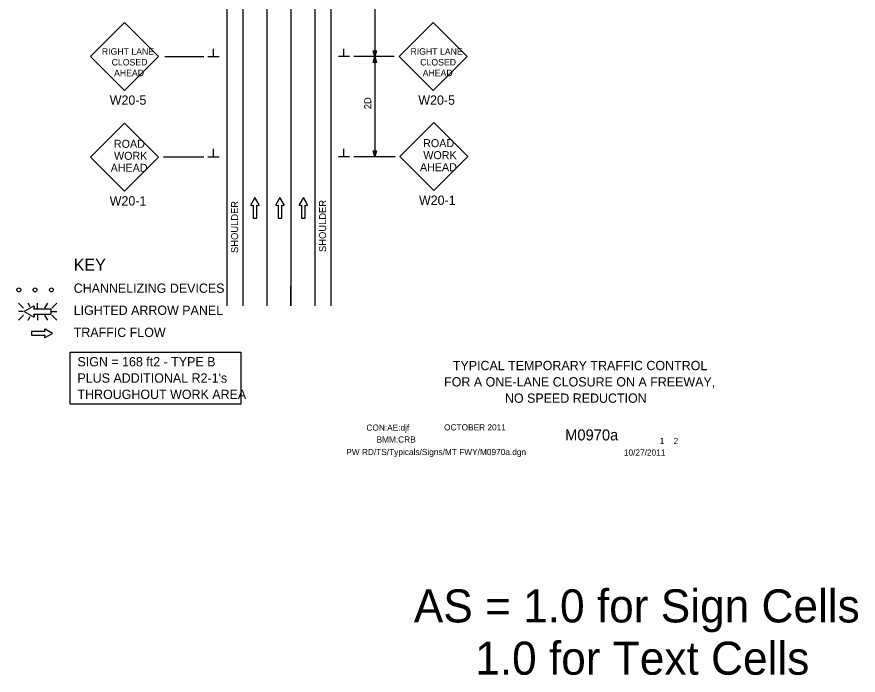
# Model space of a CAD drawing. Extents: x 16741 to 18475, y 7000 to 8315.
# Drawn here: x 16741 to 17582, y 7000 to 7658 of the extents above; entities that cross this region are included whole.
import ezdxf

# ---------------------------------------------------------------- set-up
doc = ezdxf.new("R2010")
doc.units = 0
for name, color, linetype in [('ALI_LEGAL_EX', 7, 'Continuous'), ('BORDER', 7, 'Continuous'), ('BORDER_SIGNAL_WO', 7, 'Continuous'), ('MT_SCRATCH_LEVEL_E', 7, 'Continuous'), ('PAVT_EDGE_EX', 7, 'Continuous'), ('TRAFFIC_SIGNS_PR', 7, 'Continuous'), ('TYPICAL_TEXT_DIMEN_EX', 7, 'Continuous'), ('TYPICAL_TEXT_DIMEN_PR', 7, 'Continuous')]:
    doc.layers.add(name, color=color, linetype=linetype)

msp = doc.modelspace()

# ---------------------------------------------------------------- linework, layer by layer
at = {"layer": 'ALI_LEGAL_EX'}
for p, q in [((16991.15, 8188.6), (16991.15, 7369.05)), ((17015.15, 8188.6), (17015.15, 7369.05))]:
    msp.add_line(p, q, dxfattribs=at)
for points in [[(16991.15, 7588.6), (16991.15, 7563.6)], [(17015.15, 7588.6), (17015.15, 7563.6)], [(16991.15, 7488.6), (16991.15, 7463.6)], [(17015.15, 7488.6), (17015.15, 7463.6)], [(16991.15, 7388.6), (16991.15, 7369.05)], [(17015.15, 7369.05), (17015.15, 7388.6)], [(17015.15, 7369.05), (17015.15, 7388.6)]]:
    msp.add_lwpolyline(points, dxfattribs=at)
at = {"layer": 'MT_SCRATCH_LEVEL_E'}
for p, q in [((16979.32, 7477.44), (16975.21, 7470.2)), ((16983.46, 7470.2), (16979.32, 7477.44)), ((17004.27, 7477.44), (17000.16, 7470.2)), ((17008.42, 7470.2), (17004.27, 7477.44)), ((17027.68, 7477.44), (17023.57, 7470.2)), ((17031.83, 7470.2), (17027.68, 7477.44)), ((16975.69, 7469.52), (16977.46, 7469.84)), ((16977.46, 7469.84), (16977.46, 7456.58)), ((16981.21, 7456.58), (16981.21, 7469.84)), ((16981.21, 7469.84), (16982.98, 7469.52)), ((17000.64, 7469.52), (17002.42, 7469.84)), ((17002.42, 7469.84), (17002.42, 7456.58)), ((17006.16, 7456.58), (17006.16, 7469.84)), ((17006.16, 7469.84), (17007.94, 7469.52)), ((17024.05, 7469.52), (17025.83, 7469.84)), ((17025.83, 7469.84), (17025.83, 7456.58)), ((17029.57, 7456.58), (17029.57, 7469.84)), ((17029.57, 7469.84), (17031.35, 7469.52)), ((16977.46, 7456.58), (16981.21, 7456.58)), ((17002.42, 7456.58), (17006.16, 7456.58)), ((17025.83, 7456.58), (17029.57, 7456.58)), ((16769.4, 7343.46), (16756.14, 7343.46)), ((16756.14, 7343.46), (16756.14, 7339.72)), ((16756.14, 7339.72), (16769.4, 7339.72)), ((16769.08, 7345.24), (16769.4, 7343.46)), ((16769.4, 7339.72), (16769.08, 7337.94)), ((16777.01, 7341.61), (16769.76, 7345.72)), ((16769.76, 7337.46), (16777.01, 7341.61))]:
    msp.add_line(p, q, dxfattribs=at)
for centre, start, end in [((16975.61, 7469.98), 150.42484, 279.96381), ((16983.05, 7469.98), 260.03619, 29.77312), ((17000.56, 7469.98), 150.42484, 279.96381), ((17008.01, 7469.98), 260.03619, 29.77312), ((17023.98, 7469.98), 150.42484, 279.96381), ((17031.42, 7469.98), 260.03619, 29.77312), ((16769.54, 7345.31), 60.42484, 189.96381), ((16769.54, 7337.87), 170.03619, 299.77312)]:
    msp.add_arc(centre, 0.463, start, end, dxfattribs=at)
at = {"layer": 'PAVT_EDGE_EX'}
for p, q in [((17015.15, 8314.85), (17015.15, 7485.67)), ((16951.15, 8188.6), (16951.15, 7369.05)), ((16967.15, 8188.6), (16967.15, 7369.05)), ((17039.15, 8188.6), (17039.15, 7369.05)), ((17055.15, 8188.6), (17055.15, 7369.05))]:
    msp.add_line(p, q, dxfattribs=at)
at = {"layer": 'TRAFFIC_SIGNS_PR'}
for p, q in [((16848.97, 7652.25), (16815.03, 7618.31)), ((16882.91, 7618.31), (16848.97, 7652.25)), ((17157.34, 7652.25), (17123.4, 7618.31)), ((17191.28, 7618.31), (17157.34, 7652.25)), ((16815.03, 7618.31), (16848.97, 7584.37)), ((16848.97, 7584.37), (16882.91, 7618.31)), ((17123.4, 7618.31), (17157.34, 7584.37)), ((17157.34, 7584.37), (17191.28, 7618.31)), ((16848.97, 7551.55), (16815.03, 7517.61)), ((16882.91, 7517.61), (16848.97, 7551.55)), ((17157.99, 7552.2), (17124.05, 7518.26)), ((17191.93, 7518.26), (17157.99, 7552.2)), ((16815.03, 7517.61), (16848.97, 7483.67)), ((16848.97, 7483.67), (16882.91, 7517.61)), ((17124.05, 7518.26), (17157.99, 7484.32)), ((17157.99, 7484.32), (17191.93, 7518.26)), ((16743.04, 7371.87), (16747.97, 7366.93)), ((16754.8, 7368.05), (16752.59, 7371.87)), ((16762.12, 7366.93), (16762.12, 7371.87)), ((16769.36, 7366.93), (16772.21, 7371.87)), ((16776.27, 7366.93), (16781.21, 7371.87)), ((16747.97, 7363.38), (16743.04, 7363.38)), ((16743.04, 7354.89), (16747.97, 7359.82)), ((16752.55, 7354.89), (16754.66, 7358.55)), ((16762.12, 7359.82), (16762.12, 7354.89)), ((16772.25, 7354.89), (16769.4, 7359.82)), ((16776.27, 7363.38), (16781.21, 7363.38)), ((16776.27, 7359.82), (16781.21, 7354.89))]:
    msp.add_line(p, q, dxfattribs=at)
for points in [[(16758.05, 7368.65), (16748.76, 7363.38), (16758.05, 7358.06)], [(16758.92, 7358.69), (16758.52, 7360.95), (16775.54, 7360.95), (16775.54, 7365.76), (16758.52, 7365.76), (16758.93, 7368.03)]]:
    msp.add_lwpolyline(points, dxfattribs=at)
for centre in [(16743.38, 7385.06), (16759.68, 7385.06), (16775.98, 7385.06)]:
    msp.add_circle(centre, 2, dxfattribs=at)
for centre, radius, start, end in [((16758.34, 7368.13), 0.598, 350.73078, 118.89165), ((16758.34, 7358.58), 0.597, 241.48329, 9.95933)]:
    msp.add_arc(centre, radius, start, end, dxfattribs=at)
at = {"layer": 'TYPICAL_TEXT_DIMEN_EX'}
msp.add_lwpolyline([(16794.78, 7322.66), (16965.2, 7322.66), (16965.2, 7270.92), (16794.78, 7270.92)], close=True, dxfattribs=at)
at = {"layer": 'TYPICAL_TEXT_DIMEN_PR'}
for p, q in [((17099.15, 7718.13), (17099.15, 7618.13)), ((16938.03, 7618.13), (16938.03, 7625.92)), ((17068.28, 7618.13), (17068.28, 7625.92)), ((16889.38, 7618.13), (16928.15, 7618.13)), ((16932.4, 7618.13), (16943.65, 7618.13)), ((17073.9, 7618.13), (17062.65, 7618.13)), ((17118.54, 7618.13), (17078.15, 7618.13)), ((17099.15, 7618.13), (17097.58, 7623.99)), ((17097.58, 7623.99), (17099.15, 7623.99)), ((17097.58, 7612.27), (17099.15, 7618.13)), ((17099.15, 7623.99), (17100.72, 7623.99)), ((17100.72, 7623.99), (17099.15, 7618.13)), ((17099.15, 7618.13), (17099.15, 7518.13)), ((17099.15, 7618.13), (17100.72, 7612.27)), ((17099.15, 7612.27), (17097.58, 7612.27)), ((17100.72, 7612.27), (17099.15, 7612.27)), ((16938.03, 7518.13), (16938.03, 7525.92)), ((17068.28, 7518.13), (17068.28, 7525.92)), ((16887.82, 7518.13), (16928.15, 7518.13)), ((16932.4, 7518.13), (16943.65, 7518.13)), ((17073.9, 7518.13), (17062.65, 7518.13)), ((17119.32, 7518.13), (17078.15, 7518.13)), ((17099.15, 7518.13), (17097.58, 7523.99)), ((17097.58, 7523.99), (17099.15, 7523.99)), ((17099.15, 7523.99), (17100.72, 7523.99)), ((17100.72, 7523.99), (17099.15, 7518.13))]:
    msp.add_line(p, q, dxfattribs=at)

# ---------------------------------------------------------------- texts
at = {"layer": 'BORDER'}
for s, p in [('TYPICAL TEMPORARY TRAFFIC CONTROL', (17177.02, 7304.82)), ('FOR A ONE-LANE CLOSURE ON A FREEWAY,', (17168.32, 7288.52)), ('NO SPEED REDUCTION', (17229.11, 7272.22))]:
    msp.add_text(s, height=9.3, dxfattribs=at).set_placement(p)
at = {"layer": 'BORDER_SIGNAL_WO'}
for s, height, p in [('CON:AE:djf  ', 6.2, (17090.69, 7244.31)), ('    OCTOBER 2011    ', 6.2, (17159.08, 7244.59)), ('BMM:CRB   ', 6.2, (17100.81, 7232.42)), ('    M0970a   ', 11, (17272.86, 7234.63)), (' 1    2 ', 6.2, (17381.45, 7230.95)), ('PW RD/TS/Typicals/Signs/MT FWY/M0970a.dgn      ', 6.2, (17070.55, 7219.96)), ('10/27/2011    ', 6.2, (17347.93, 7219.38)), ('AS = 1.0 for Sign Cells', 33.0301, (17138.06, 7052.73)), ('     1.0 for Text Cells', 33.0301, (17138.06, 7000.5))]:
    msp.add_text(s, height=height, dxfattribs=at).set_placement(p)
at = {"layer": 'TRAFFIC_SIGNS_PR'}
for s, height, p in [('RIGHT LANE', 6.5, (16826.37, 7620.06)), ('RIGHT LANE', 6.5, (17134.74, 7620.06)), ('CLOSED', 6.5, (16836.11, 7609.31)), ('CLOSED', 6.5, (17144.48, 7609.31)), ('AHEAD', 6.5, (16838.54, 7598.56)), ('AHEAD', 6.5, (17146.91, 7598.56)), ('W20-5', 9.3, (16834.19, 7570.07)), ('W20-5', 9.3, (17142.55, 7570.07)), ('ROAD', 8, (16838.4, 7527.03)), ('ROAD', 8, (17147.41, 7527.68)), ('WORK', 8, (16838.53, 7515.03)), ('WORK', 8, (17147.55, 7515.68)), ('AHEAD', 8, (16835.17, 7503.03)), ('AHEAD', 8, (17144.19, 7503.68)), ('W20-1', 9.3, (16834.18, 7469.37)), ('W20-1', 9.3, (17143.2, 7470.02))]:
    msp.add_text(s, height=height, dxfattribs=at).set_placement(p)
at = {"layer": 'TYPICAL_TEXT_DIMEN_EX'}
for s, height, p in [('KEY', 12, (16798.22, 7404.17)), ('CHANNELIZING DEVICES', 9.3, (16798.22, 7382.12)), ('LIGHTED ARROW PANEL', 9.3, (16798.22, 7360.07)), ('TRAFFIC FLOW', 9.3, (16798.22, 7338.02)), ('SIGN = 168 ft2 - TYPE B', 9.3, (16801.97, 7308.63)), ("PLUS ADDITIONAL R2-1's", 9.3, (16801.97, 7292.33)), ('THROUGHOUT WORK AREA', 9.3, (16801.97, 7276.03))]:
    msp.add_text(s, height=height, dxfattribs=at).set_placement(p)
at = {"layer": 'TYPICAL_TEXT_DIMEN_PR'}
for s, p in [('2D', (17095.48, 7565.61)), ('SHOULDER', (17050.43, 7422.94)), ('SHOULDER', (16962.51, 7421.95))]:
    msp.add_text(s, height=7, rotation=90, dxfattribs=at).set_placement(p)

doc.saveas('drawing.dxf')
